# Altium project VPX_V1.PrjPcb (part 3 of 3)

## Sheet Telemetry.SchDoc
size 431 x 279 mm; Date: Not shown in title block; ApprovedBy: Not shown in title block; CheckedBy: Not shown in title block; Author: Not shown in title block; CompanyName: Not shown in title block; Engineer: Not shown in title block; Organization: Not shown in title block; Address1: Not shown in title block; Address2: Not shown in title block; Address3: Not shown in title block; Address4: Not shown in title block; DocumentNumber: 1; Revision: Use project parameter SCH_Rev; SheetNumber: 7; SheetTotal: 8; PageSetup: Record=PageOptions¦CenterHorizontal=True¦CenterVertical=True¦PrintScale=1.00¦XCorrection=1.00¦YCorrection=1.00¦PrintKind=0¦BorderSize=5000000¦LeftOffset=0¦BottomOffset=0¦Orientation=2¦PaperLength=1000¦PaperWidth=1000¦Scale=100¦PaperSource=15¦PrintQuality=600¦MediaType=1¦DitherType=10¦PaperKind=Letter¦PrintScaleMode=1
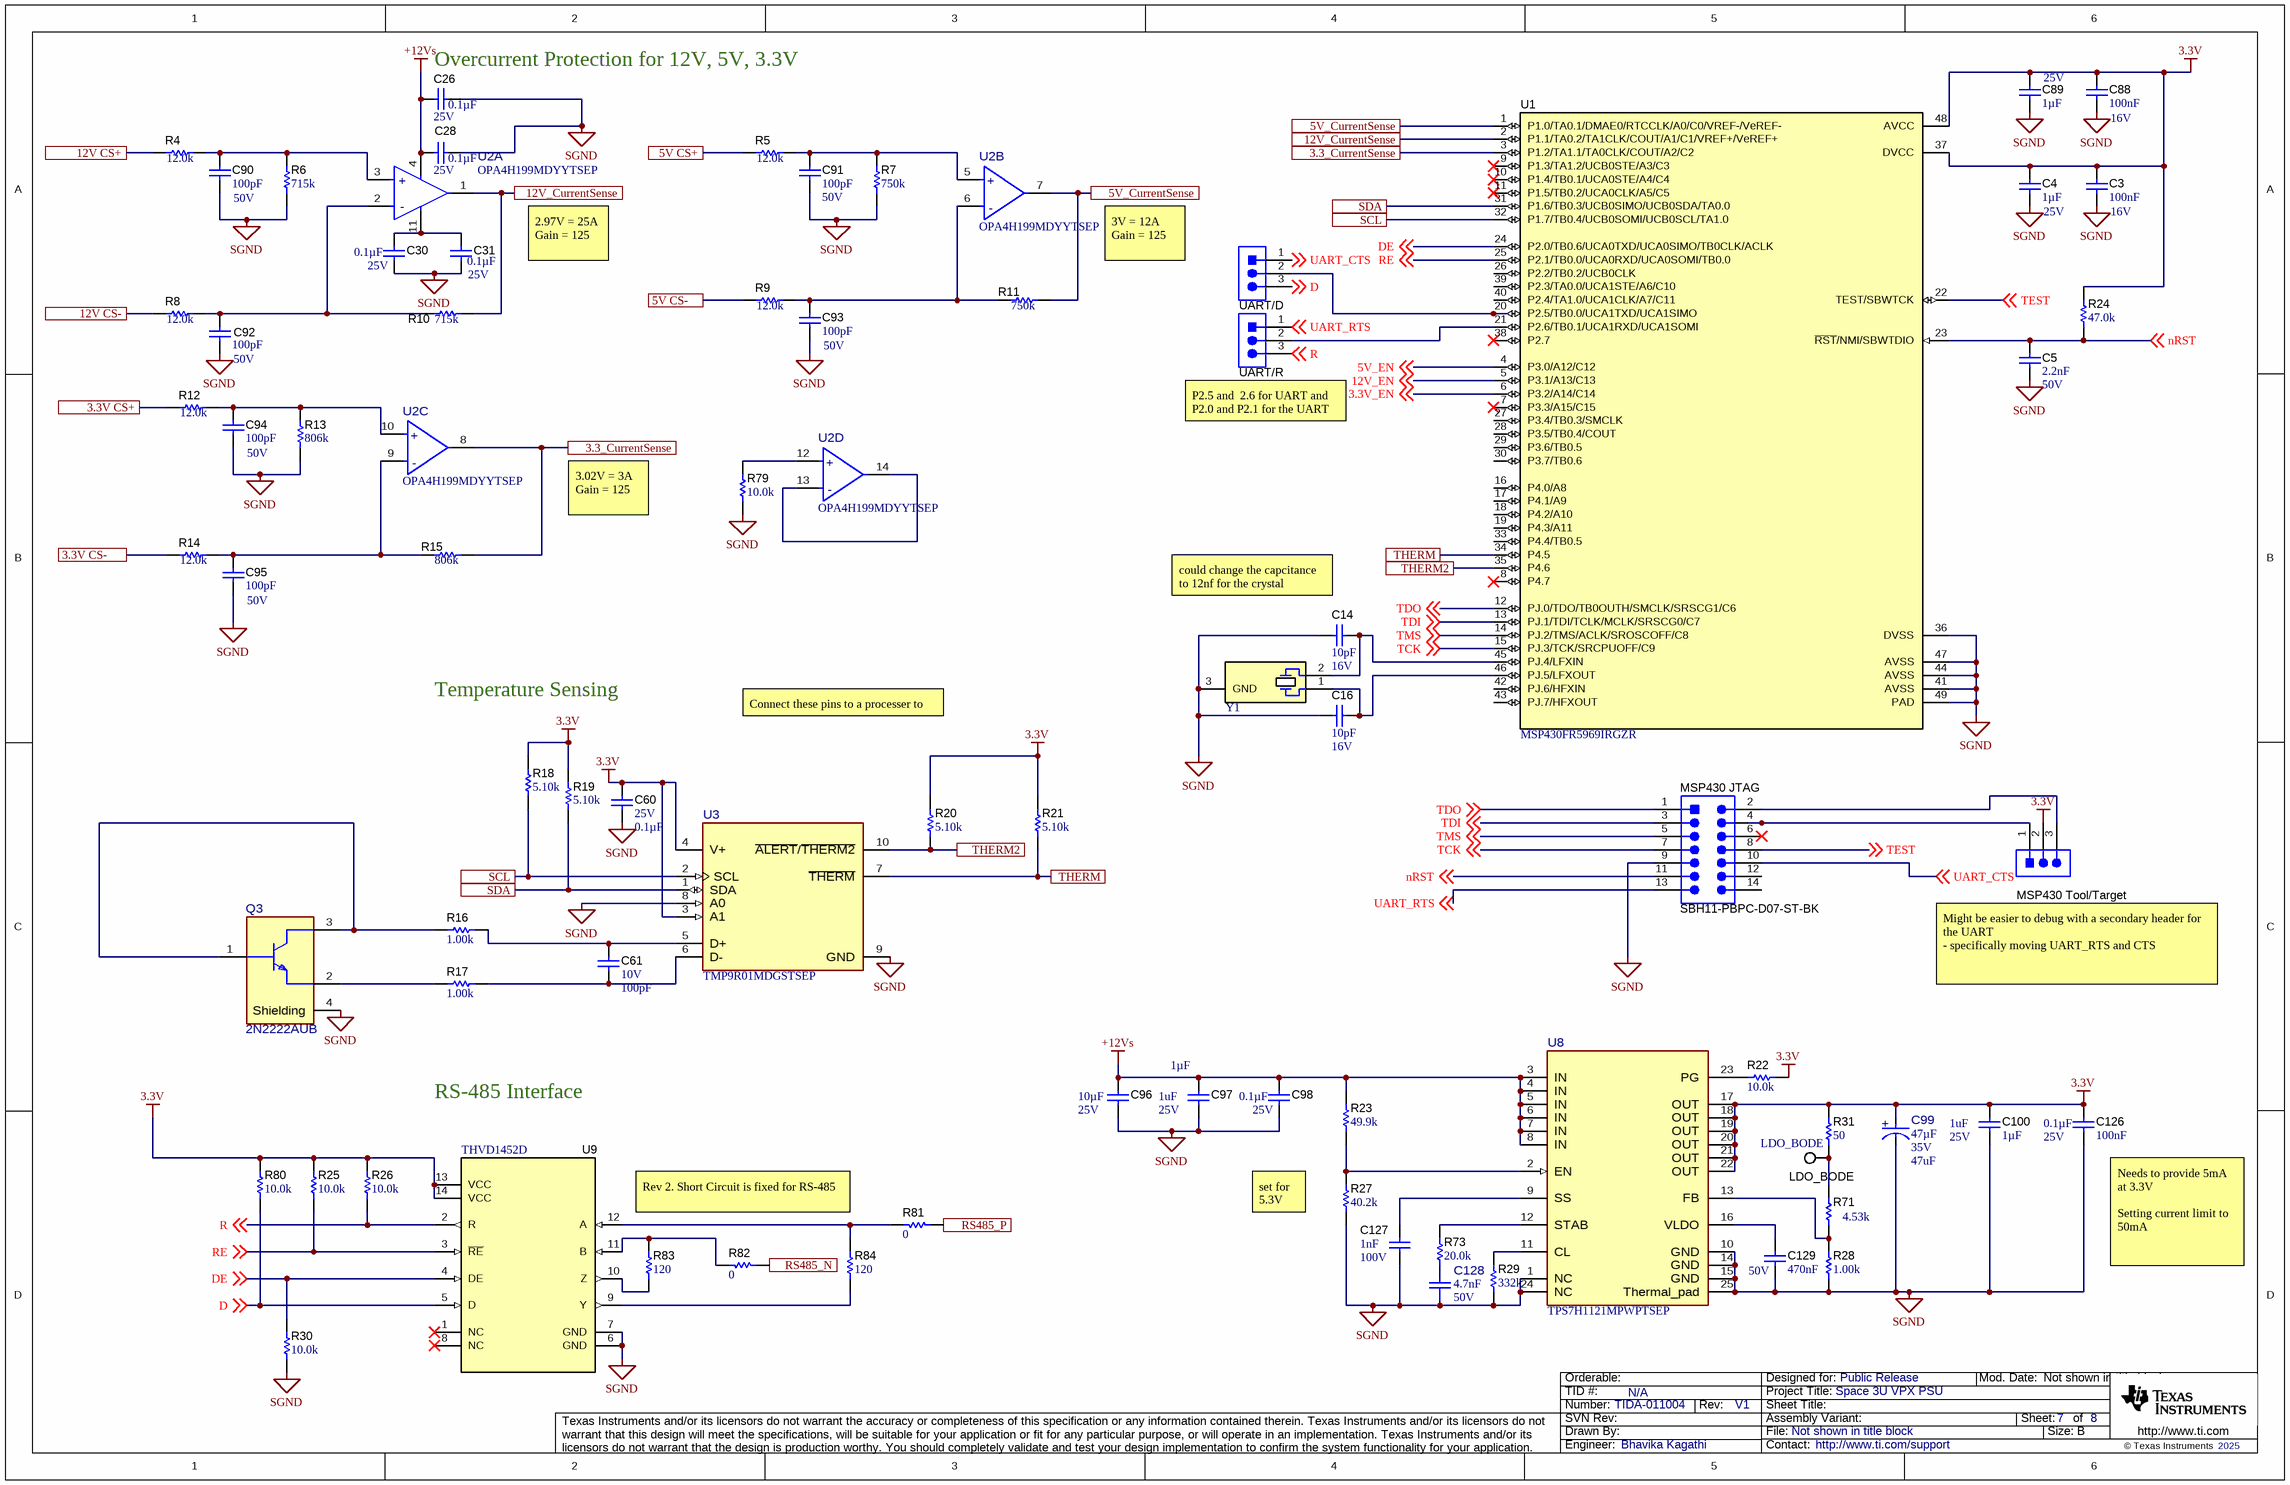
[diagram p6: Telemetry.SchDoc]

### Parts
C3  Cap_F: 100nF  VDC_V: 16V  [0603]  (hidden comment: CL10B104KO8WPNC)
C4  Cap_F: 1µF  VDC_V: 25V  [0603]  (hidden comment: C0603C105K3RACTU)
C5  Cap_F: 2.2nF  VDC_V: 50V  [0603]  (hidden comment: C0603X222K5RACTU)
C14  Cap_F: 10pF  VDC_V: 16V  [0402]  (hidden comment: C0402C100K4GACTU)
C16  Cap_F: 10pF  VDC_V: 16V  [0402]  (hidden comment: C0402C100K4GACTU)
C26  VDC_V: 25V  ValueDisplayed: 0.1µF  [0603]  (hidden comment: GCM188R71E104KA57D)
C28  VDC_V: 25V  ValueDisplayed: 0.1µF  [0603]  (hidden comment: GCM188R71E104KA57D)
C30  VDC_V: 25V  ValueDisplayed: 0.1µF  [0603]  (hidden comment: GCM188R71E104KA57D)
C31  VDC_V: 25V  ValueDisplayed: 0.1µF  [0603]  (hidden comment: GCM188R71E104KA57D)
C60  VDC_V: 25V  ValueDisplayed: 0.1µF  [0603]  (hidden comment: GCM188R71E104KA57D)
C61  VDC_V: 10V  ValueDisplayed: 100pF  [0603]  (hidden comment: 0603ZC101KAT2A)
C88  Cap_F: 100nF  VDC_V: 16V  [0603]  (hidden comment: CL10B104KO8WPNC)
C89  Cap_F: 1µF  VDC_V: 25V  [0603]  (hidden comment: C0603C105K3RACTU)
C90  Cap_F: 100pF  VDC_V: 50V  [0603L]  (hidden comment: CL10B101KB8NNNC)
C91  Cap_F: 100pF  VDC_V: 50V  [0603L]  (hidden comment: CL10B101KB8NNNC)
C92  Cap_F: 100pF  VDC_V: 50V  [0603L]  (hidden comment: CL10B101KB8NNNC)
C93  Cap_F: 100pF  VDC_V: 50V  [0603L]  (hidden comment: CL10B101KB8NNNC)
C94  Cap_F: 100pF  VDC_V: 50V  [0603L]  (hidden comment: CL10B101KB8NNNC)
C95  Cap_F: 100pF  VDC_V: 50V  [0603L]  (hidden comment: CL10B101KB8NNNC)
C96  VDC_V: 25V  ValueDisplayed: 10µF  [0603]  (hidden comment: GRM188R61E106KA73D)
C97  VDC_V: 25V  ValueDisplayed: 1uF  Cap_F: 1µF  [0603]  (hidden comment: C0603C105K3RACTU)
C98  VDC_V: 25V  ValueDisplayed: 0.1µF  [0603]  (hidden comment: GCM188R71E104KA57D)
C99  Cap_F: 47µF  VDC_V: 35V  ValueDisplayed: 47uF  [FP-T510X476M035ATE055_2917-MFG]  (hidden comment: T510X476M035ATE055)
C100  Cap_F: 1µF  VDC_V: 25V  ValueDisplayed: 1uF  [0603]  (hidden comment: C0603C105K3RACTU)
C126  Cap_F: 100nF  VDC_V: 25V  ValueDisplayed: 0.1µF  [0603]  (hidden comment: GCM188R71E104KA57D)
C127  Cap_F: 1nF  VDC_V: 100V  [0603]  (hidden comment: 06031C102JAT2A)
C128  Cap_F: 4.7nF  VDC_V: 50V  [FP-C0603C472J5RAC7867_0603-MFG]  (hidden comment: C0603C472J5RAC7867)
C129  Cap_F: 470nF  VDC_V: 50V  [0603]  (hidden comment: UMK107B7474KA-TR)
LDO_BODE  LDO_BODE  [Keystone5002]
MSP430_JTAG  SBH11-PBPC-D07-ST-BK  [CONN_SBH11-PBPC-D07-ST-BK]
MSP430_Tool/Target  PTT-103-01-L-S  [Samtec_PTT-103-01-x-S]  (value not drawn)
Q3  2N2222AUB  [FP-2N2222AUB_SMT3-IPC_A]
R4  ValueDisplayed: 12.0k  [0603]  (hidden comment: RC0603FR-0712KL)
R5  ValueDisplayed: 12.0k  [0603]  (hidden comment: RC0603FR-0712KL)
R6  ValueDisplayed: 715k  [0603]  (hidden comment: CRCW0603715KFKEA)
R7  ValueDisplayed: 750k  [0603]  (hidden comment: CRCW0603750KFKEA)
R8  ValueDisplayed: 12.0k  [0603]  (hidden comment: RC0603FR-0712KL)
R9  ValueDisplayed: 12.0k  [0603]  (hidden comment: RC0603FR-0712KL)
R10  ValueDisplayed: 715k  [0603]  (hidden comment: CRCW0603715KFKEA)
R11  ValueDisplayed: 750k  [0603]  (hidden comment: CRCW0603750KFKEA)
R12  ValueDisplayed: 12.0k  [0603]  (hidden comment: RC0603FR-0712KL)
R13  ValueDisplayed: 806k  [0603]  (hidden comment: CRCW0603806KFKEA)
R14  ValueDisplayed: 12.0k  [0603]  (hidden comment: RC0603FR-0712KL)
R15  ValueDisplayed: 806k  [0603]  (hidden comment: CRCW0603806KFKEA)
R16  ValueDisplayed: 1.00k  [0603]  (hidden comment: RC0603FR-071KL)
R17  ValueDisplayed: 1.00k  [0603]  (hidden comment: RC0603FR-071KL)
R18  ValueDisplayed: 5.10k  [0603]  (hidden comment: RC0603FR-075K1L)
R19  ValueDisplayed: 5.10k  [0603]  (hidden comment: RC0603FR-075K1L)
R20  ValueDisplayed: 5.10k  [0603]  (hidden comment: RC0603FR-075K1L)
R21  ValueDisplayed: 5.10k  [0603]  (hidden comment: RC0603FR-075K1L)
R22  ValueDisplayed: 10.0k  [0603]  (hidden comment: RC0603FR-0710KL)
R23  ValueDisplayed: 49.9k  [0603]  (hidden comment: ERJ-3EKF4992V)
R24  ValueDisplayed: 47.0k  [0603]  (hidden comment: RC0603FR-0747KL)
R25  ValueDisplayed: 10.0k  [0603]  (hidden comment: CRCW060310K0FKEA)
R26  ValueDisplayed: 10.0k  [0603]  (hidden comment: CRCW060310K0FKEA)
R27  ValueDisplayed: 40.2k  [0603]  (hidden comment: RC0603FR-0740K2L)
R28  ValueDisplayed: 1.00k  [0603]  (hidden comment: CRCW06031K00FKEA)
R29  ValueDisplayed: 332k  [0603]  (hidden comment: CRCW0603332KFKEA)
R30  ValueDisplayed: 10.0k  [0603]  (hidden comment: CRCW060310K0FKEA)
R31  ValueDisplayed: 50  [0603]  (hidden comment: FC0603E50R0BTBST1)
R71  ValueDisplayed: 4.53k  [0603]  (hidden comment: ERJ-3EKF4531V)
R73  ValueDisplayed: 20.0k  [0603]  (hidden comment: RG1608P-203-B-T5)
R79  ValueDisplayed: 10.0k  [0603]  (hidden comment: RT0603BRD0710KL)
R80  ValueDisplayed: 10.0k  [0603]  (hidden comment: CRCW060310K0FKEA)
R81  ValueDisplayed: 0  [0603_HV]  (hidden comment: CRCW06030000Z0EA)
R82  ValueDisplayed: 0  [0603_HV]  (hidden comment: CRCW06030000Z0EA)
R83  ValueDisplayed: 120  [0603]  (hidden comment: RC0603FR-07120RL)
R84  ValueDisplayed: 120  [0603]  (hidden comment: RC0603FR-07120RL)
U1  MSP430FR5969IRGZR  [RGZ0048B]
U2  OPA4H199MDYYTSEP  [DYY0014A-MFG]  (parts A,B,C,D of 4)
U3  TMP9R01MDGSTSEP  [DGS0010A-MFG]
U8  TPS7H1121MPWPTSEP  [PWP0024R-MFG]
U9  THVD1452D  [D0014A_N]
UART/D  PTT-103-01-L-S  [Samtec_PTT-103-01-x-S]  (value not drawn)
UART/R  PTT-103-01-L-S  [Samtec_PTT-103-01-x-S]  (value not drawn)
Y1  MS3V-T1R 32.768KHZ 7.0 PF  [XTAL_MS3V-T1R]  (value not drawn)

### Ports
3.3_CurrentSense, 3.3V CS+, 3.3V CS-, 5V CS+, 5V CS-, 5V_CurrentSense, 12V CS+, 12V CS-, 12V_CurrentSense, RS485_N, RS485_P, SCL, SDA, THERM, THERM2

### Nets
3.3V: C3.1 C4.1 C60.2 C88.1 C89.1 C99.2(ANODE) C100.1 C126.1 MSP430_Tool/Target.2 R18.1 R19.1 R20.1 R21.1 R22.2 R24.1 R25.1 R26.1 R31.2 R80.1 U1.37(DVCC) U1.48(AVCC) U3.3(A1) U3.4(V+) U8.17(OUT) U8.18(OUT) U8.19(OUT) U8.20(OUT) U8.21(OUT) U8.22(OUT) U9.13(VCC) U9.14(VCC)
3.3V_OUT: R14.2 ; port 3.3V CS-
5V: R9.2 ; port 5V CS-
+12Vs: C26.1 C28.2 C96.1 C97.1 C98.1 R23.1 U2.4(V+) U8.3(IN) U8.4(IN) U8.5(IN) U8.6(IN) U8.7(IN) U8.8(IN)
PVIN: R8.2 ; port 12V CS-
SGND: C3.2 C4.2 C5.1 C14.1 C16.1 C26.2 C28.1 C30.2 C31.2 C60.1 C88.2 C89.2 C90.2 C91.2 C92.2 C93.2 C94.2 C95.2 C96.2 C97.2 C98.2 C99.1(CATHODE) C100.2 C126.2 C127.2 C128.1 C129.2 MSP430_JTAG.9 Q3.4(Shielding) R6.2 R7.2 R13.2 R27.2 R28.2 R29.2 R30.2 R79.1 U1.36(DVSS) U1.41(AVSS) U1.44(AVSS) U1.47(AVSS) U1.49(PAD) U3.8(A0) U3.9(GND) U8.1(NC) U8.10(GND) U8.14(GND) U8.15(GND) U8.24(NC) U8.25(Thermal_pad) U9.6(GND) U9.7(GND) Y1.3(GND)
3.3_CurrentSense: R15.1 U1.3(P1.2/TA1.1/TA0CLK/COUT/A2/C2) U2.8(OUT3) ; port 3.3_CurrentSense
3.3V CS+: R12.2 ; port 3.3V CS+
3.3V_EN: U1.6(P3.2/A14/C14) ; off-sheet 3.3V_EN
5V CS+: R5.2 ; port 5V CS+
5V_CurrentSense: R11.1 U1.1(P1.0/TA0.1/DMAE0/RTCCLK/A0/C0/VREF-/VeREF-) U2.7(OUT2) ; port 5V_CurrentSense
5V_EN: U1.4(P3.0/A12/C12) ; off-sheet 5V_EN
12V CS+: R4.2 ; port 12V CS+
12V_CurrentSense: R10.1 U1.2(P1.1/TA0.2/TA1CLK/COUT/A1/C1/VREF+/VeREF+) U2.1(OUT1) ; port 12V_CurrentSense
12V_EN: U1.5(P3.1/A13/C13) ; off-sheet 12V_EN
D: R80.2 U9.5(D) UART/D.3 ; off-sheet D
DE: R30.1 U1.24(P2.0/TB0.6/UCA0TXD/UCA0SIMO/TB0CLK/ACLK) U9.4(DE) ; off-sheet DE
nRST: C5.2 MSP430_JTAG.11 R24.2 U1.23(~{RST}/NMI/SBWTDIO) ; off-sheet nRST
R: R26.2 U9.2(R) UART/R.3 ; off-sheet R
RE: R25.2 U1.25(P2.1/TB0.0/UCA0RXD/UCA0SOMI/TB0.0) U9.3(~{RE}) ; off-sheet RE
RS485_N: R82.2 ; port RS485_N
RS485_P: R81.2 ; port RS485_P
SCL: R18.2 U1.32(P1.7/TB0.4/UCB0SOMI/UCB0SCL/TA1.0) U3.2(SCL) ; port SCL
SDA: R19.2 U1.31(P1.6/TB0.3/UCB0SIMO/UCB0SDA/TA0.0) U3.1(SDA) ; port SDA
TCK: MSP430_JTAG.7 U1.15(PJ.3/TCK/SRCPUOFF/C9) ; off-sheet TCK
TDI: MSP430_JTAG.3 U1.13(PJ.1/TDI/TCLK/MCLK/SRSCG0/C7) ; off-sheet TDI
TDO: MSP430_JTAG.1 U1.12(PJ.0/TDO/TB0OUTH/SMCLK/SRSCG1/C6) ; off-sheet TDO
TEST: MSP430_JTAG.8 U1.22(TEST/SBWTCK) ; off-sheet TEST
THERM: R21.2 U1.34(P4.5) U3.7(~{THERM}) ; port THERM
THERM2: R20.2 U1.35(P4.6) U3.10(~{ALERT}/~{THERM2}) ; port THERM2
TMS: MSP430_JTAG.5 U1.14(PJ.2/TMS/ACLK/SROSCOFF/C8) ; off-sheet TMS
UART_CTS: MSP430_JTAG.10 UART/D.1 ; off-sheet UART_CTS
UART_RTS: MSP430_JTAG.13 UART/R.1 ; off-sheet UART_RTS
NetC14_2: C14.2 U1.45(PJ.4/LFXIN) Y1.2
NetC16_2: C16.2 U1.46(PJ.5/LFXOUT) Y1.1
NetC30_1: C30.1 C31.1 U2.11(V-)
NetC61_1: C61.1 R17.2 U3.6(D-)
NetC61_2: C61.2 R16.2 U3.5(D+)
NetC90_1: C90.1 R4.1 R6.1 U2.3(IN1+)
NetC91_1: C91.1 R5.1 R7.1 U2.5(IN2+)
NetC92_1: C92.1 R8.1 R10.2 U2.2(IN1-)
NetC93_1: C93.1 R9.1 R11.2 U2.6(IN2-)
NetC94_1: C94.1 R12.1 R13.1 U2.10(IN3+)
NetC95_1: C95.1 R14.1 R15.2 U2.9(IN3-)
NetC127_1: C127.1 U8.9(SS)
NetC128_2: C128.2 R73.2
NetC129_1: C129.1 U8.16(VLDO)
NetLDO_BODE_1: LDO_BODE.1 R31.1 R71.1
NetMSP430_JTAG_2: MSP430_JTAG.2 MSP430_Tool/Target.3
NetMSP430_JTAG_4: MSP430_JTAG.4 MSP430_Tool/Target.1
NetQ3_1: Q3.1(Base) Q3.3(Collector) R16.1
NetQ3_2: Q3.2(Emitter) R17.1
NetR22_1: R22.1 U8.23(PG)
NetR23_2: R23.2 R27.1 U8.2(EN)
NetR28_1: R28.1 R71.2 U8.13(FB)
NetR29_1: R29.1 U8.11(CL)
NetR73_1: R73.1 U8.12(STAB)
NetR79_2: R79.2 U2.12(IN4+)
NetR81_1: R81.1 R84.2 U9.12(A)
NetR82_1: R82.1 R83.2 U9.11(B)
NetR83_1: R83.1 U9.10(Z)
NetR84_1: R84.1 U9.9(Y)
NetU1_20: U1.20(P2.5/TB0.0/UCA1TXD/UCA1SIMO) UART/D.2
NetU1_21: U1.21(P2.6/TB0.1/UCA1RXD/UCA1SOMI) UART/R.2
NetU2_13: U2.13(IN4-) U2.14(OUT4)

Not connected (* = marked no-connect by the designer): MSP430_JTAG 6* 12 14; U1 7(P3.3/A15/C15)* 8(P4.7)* 9(P1.3/TA1.2/UCB0STE/A3/C3)* 10(P1.4/TB0.1/UCA0STE/A4/C4)* 11(P1.5/TB0.2/UCA0CLK/A5/C5)* 16(P4.0/A8) 17(P4.1/A9) 18(P4.2/A10) 19(P4.3/A11) 26(P2.2/TB0.2/UCB0CLK) 27(P3.4/TB0.3/SMCLK) 28(P3.5/TB0.4/COUT) 29(P3.6/TB0.5) 30(P3.7/TB0.6) 33(P4.4/TB0.5) 38(P2.7)* 39(P2.3/TA0.0/UCA1STE/A6/C10) 40(P2.4/TA1.0/UCA1CLK/A7/C11) 42(PJ.6/HFXIN) 43(PJ.7/HFXOUT); U9 1(NC)* 8(NC)*

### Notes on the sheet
- (near C26) Overcurrent Protection for 12V, 5V, 3.3V
- 2.97V = 25A
  Gain = 125
- 3V = 12A
  Gain = 125
- (near UART/R) P2.5 and  2.6 for UART and P2.0 and P2.1 for the UART channel
- 3.02V = 3A
  Gain = 125
- (near C14) could change the capcitance to 12nf for the crystal
- Temperature Sensing
- Connect these pins to a processer to pins with interrupt
- Might be easier to debug with a secondary header for the UART
  - specifically moving UART_RTS and CTS
- RS-485 Interface
- Rev 2. Short Circuit is fixed for RS-485
- set for 5.3V
- (near C126) Needs to provide 5mA at 3.3V
  Setting current limit to 50mA

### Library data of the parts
C3 C88 = CMP-0085536-1: CAP, CERM, 0.1 µF, 16 V,+/- 10%, X7R, 0603; Manufacturer: Samsung Electro-Mechanics; SizeArea_mm2: 1.28; SizeY_mm: 0.8; AEC Category: Q200; Polarized: N; AEC Qualified: Y; ValueDisplayed: 0.1µF; TaMax_C: 125°C; SizeZ_mm: 1; U/M: EA; SizeX_mm: 1.6; Value: 0.1uF; TaMin_C: -55°C; SizeAreaWB_mm2: 4.68
C4 C89 = CMP-0006867-4: CAP, CERM, 1 uF, 25 V, +/- 10%, X7R, 0603; Manufacturer: Kemet; TaMin_C: -55°C; Polarized: N; SizeAreaWB_mm2: 4.68; Value1: Unknown; U/M: EA; Value: 1uF; TaMax_C: 125°C; SizeZ_mm: 1; SizeX_mm: 1.6; SizeY_mm: 0.8; SizeArea_mm2: 1.28; AEC Category: Q200
C5 = CMP-0006983-4: CAP, CERM, 2200 pF, 50 V, +/- 10%, X7R, 0603; Manufacturer: Kemet; Value1: Unknown; ValueDisplayed: 2200pF; SizeZ_mm: 1; AEC Category: Q200; TaMin_C: -55°C; SizeY_mm: 0.8; Polarized: N; SizeAreaWB_mm2: 4.68; SizeArea_mm2: 1.28; TaMax_C: 125°C; SizeX_mm: 1.6; Value: 2200pF; U/M: EA
C14 C16 = CMP-0079539-1: CAP, CERM, 10 pF, 16 V,+/- 10%, C0G, 0402; Manufacturer: Kemet; SizeZ_mm: 0.6; AEC Category: Q200; AEC Qualified: N; Green_REACh: Passed; TaMin_C: -55°C; Green_Lifecycle: Active; SizeY_mm: 0.5; SizeAreaWB_mm2: 3; TaMax_C: 125°C; SizeX_mm: 1; Value: 10pF; U/M: EA
C26 C28 C30 C31 C60 C98 C126 = CMP-0084679-1: CAP, CERM, 0.1 µF, 25 V,+/- 10%, X7R, AEC-Q200 Grade 1, 0603; Manufacturer: MuRata; SizeZ_mm: 1; AEC Category: Q200; AEC Qualified: Y; TaMin_C: -55°C; SizeY_mm: 0.8; Polarized: N; SizeAreaWB_mm2: 4.68; SizeArea_mm2: 1.28; TaMax_C: 125°C; SizeX_mm: 1.6; Value: 0.1uF; U/M: EA
C61 = CMP-0006812-4: CAP, CERM, 100 pF, 10 V, +/- 10%, X7R, 0603; Manufacturer: AVX; Value1: Unknown; SizeZ_mm: 1; AEC Category: Q200; AEC Qualified: N; TaMin_C: -55°C; SizeY_mm: 0.8; SizeAreaWB_mm2: 4.68; SizeArea_mm2: 1.28; TaMax_C: 125°C; SizeX_mm: 1.6; Value: 100pF; U/M: EA
C90-C95 = CMP-0083857-1: CAP, CERM, 100 pF, 50 V,+/- 10%, X7R, 0603; Manufacturer: Samsung Electro-Mechanics; TaMin_C: -55°C; Polarized: N; SizeAreaWB_mm2: 4.68; U/M: EA; Value: 100pF; TaMax_C: 125°C; SizeZ_mm: 1; SizeX_mm: 1.6; SizeY_mm: 0.8; Cap_Case: 0603; SizeArea_mm2: 1.28; AEC Category: Q200
C96 = CMP-0860569-1: CAP, CERM, 10 µF, 25 V,+/- 10%, X5R, 0603; Manufacturer: MuRata; SizeZ_mm: 1; AEC Category: Q200; AEC Qualified: N; TaMin_C: -55°C; SizeY_mm: 0.8; SizeAreaWB_mm2: 4.68; SizeArea_mm2: 1.28; TaMax_C: 85°C; SizeX_mm: 1.6; Value: 10uF; U/M: EA
C97 C100 = CMP-0006867-4: CAP, CERM, 1 uF, 25 V, +/- 10%, X7R, 0603; Manufacturer: Kemet; Value1: Unknown; SizeZ_mm: 1; AEC Category: Q200; TaMin_C: -55°C; SizeY_mm: 0.8; Polarized: N; SizeAreaWB_mm2: 4.68; SizeArea_mm2: 1.28; TaMax_C: 125°C; SizeX_mm: 1.6; Value: 1uF; U/M: EA
C99 = CMP-0121724-1: 47 µF Molded Tantalum Capacitors 35 V 2917 (7343 Metric) 55mOhm; Manufacturer: Kemet; SizeZ_mm: 4.3mm; AEC Qualified: No; IRMS_A: 2.216A; Value: 47µF; Tolerance_%: 20%; Esr: 55m; Leakage Current: 16.5uA; Life: 2000Hours
C127 = CMP-0006723-4: CAP, CERM, 1000 pF, 100 V, +/- 5%, X7R, 0603; Manufacturer: AVX; TaMin_C: -55°C; Polarized: N; SizeAreaWB_mm2: 4.68; Value1: 0.276 ohm; U/M: EA; Value: 1000pF; TaMax_C: 125°C; SizeZ_mm: 1; SizeX_mm: 1.6; SizeY_mm: 0.8; SizeArea_mm2: 1.28; AEC Category: Q200; ESR_ohm: 0.276
C128 = CMP-0120173-1: 4700 pF ±5% 50V Ceramic Capacitor X7R 0603 (1608 Metric); Manufacturer: KEMET; TempCo: 15%; Value: 4.7nF; SizeZ_mm: 0.87mm; AEC Qualified: No; ValueDisplayed: 4700pF
C129 = CMP-0007509-4: CAP, CERM, 0.47 uF, 50 V, +/- 10%, X7R, 0603; Manufacturer: Taiyo Yuden; TaMin_C: -55°C; Polarized: N; SizeAreaWB_mm2: 4.68; Value1: Unknown; U/M: EA; Value: 0.47uF; TaMax_C: 125°C; SizeZ_mm: 1; SizeX_mm: 1.6; SizeY_mm: 0.8; SizeArea_mm2: 1.28; AEC Category: Q200
LDO_BODE = CMP-0055139-2: Test Point, Miniature, White, TH; Manufacturer: Keystone Electronics; ContactFinish: Silver; CT: TRUE; CNHeader: FALSE; Green_Lifecycle: Active; Green_REACh: Passed
MSP430_JTAG = CMP-0054695-2: Header (shrouded), 100 mil, 7x2, Gold, TH; Manufacturer: Sullins Connector Solutions; Green_REACh: Incomplete; Green_Lifecycle: Not Set
MSP430_Tool/Target UART/D UART/R = CMP-0055571-1: Header, 2mm, 3x1, Gold, TH; Manufacturer: Samtec; Current_A: 2.9A; Shrouded: N; CT: FALSE; Cert_UL: Y; Pitch_mm: 2; CNHeader: TRUE; Gender: Male
Q3 = CMP-0098458-1: Bipolar (BJT) Transistor NPN 50 V 800 mA 500 mW Surface Mount 3-SMD; Manufacturer: Microchip; Vcesat1_V: 1V; IcRated_A: 800mA; SizeZ_mm: 1.42mm; AEC Qualified: No; HfeMax: 300; Value: 50V; NPN: 1; Collector Base Voltage: 75V; Emitter Base Voltage: 6V; Hfe Min: 100; Hfe Ss Min: 50; Hfe Ss Testic: 1mA; Hfe Ss Testvce: 10V; Hfe Testic: 150mA; Power_W: 0.5W; Rthja Max: 325°C/W; TJmax_C: +200°C
R4 R5 R8 R9 R12 R14 = CMP-0022779-5: RES, 12.0 k, 1%, 0.1 W, 0603; Manufacturer: Yageo; Power_W: 100mW; TempCo: 100 ppm/C; Value: 12.0k; Res_ohm: 12k; SizeZ_mm: 1; AEC Qualified: N; VDC_V: 75V; Value_Code: 12k0; SizeX_mm: 1.6; SizeY_mm: 0.8; Value2: 0.1W; SizeArea_mm2: 1.28; AEC Category: Q200; SizeAreaWB_mm2: 4.68
R6 R10 = CMP-0022579-4: RES, 715 k, 1%, 0.1 W, AEC-Q200 Grade 0, 0603; Manufacturer: Vishay-Dale; Power_W: 100mW; TempCo: 100 ppm/C; Value: 715k; SizeZ_mm: 1; AEC Qualified: Y; VDC_V: 75V; AEC Grade: 0; EIA_Code: E96; SizeX_mm: 1.6; SizeY_mm: 0.8; Value2: 0.1W; SizeArea_mm2: 1.28; AEC Category: Q200
R7 R11 = CMP-0022587-4: RES, 750 k, 1%, 0.1 W, AEC-Q200 Grade 0, 0603; Manufacturer: Vishay-Dale; Power_W: 100mW; TempCo: 100 ppm/C; Value: 750k; SizeZ_mm: 1; AEC Qualified: Y; VDC_V: 75V; AEC Grade: 0; EIA_Code: E96; SizeX_mm: 1.6; SizeY_mm: 0.8; Value2: 0.1W; SizeArea_mm2: 1.28; AEC Category: Q200
R13 R15 = CMP-0022614-3: RES, 806 k, 1%, 0.1 W, AEC-Q200 Grade 0, 0603; Manufacturer: Vishay-Dale; Power_W: 100mW; TempCo: 100 ppm/C; Value: 806k; SizeZ_mm: 1; AEC Qualified: Y; VDC_V: 75V; AEC Grade: 0; EIA_Code: E96; SizeX_mm: 1.6; SizeY_mm: 0.8; Value2: 0.1W; SizeArea_mm2: 1.28; AEC Category: Q200
R16 R17 = CMP-0022895-5: RES, 1.00 k, 1%, 0.1 W, 0603; Manufacturer: Yageo; Power_W: 100mW; TempCo: 100 ppm/C; Value: 1.00k; Res_ohm: 1k; SizeZ_mm: 1; AEC Qualified: N; VDC_V: 75V; Value_Code: 1k00; EIA_Code: E96; SizeX_mm: 1.6; SizeY_mm: 0.8; Value2: 0.1W; SizeArea_mm2: 1.28; AEC Category: Q200; SizeAreaWB_mm2: 4.68
R18-R21 = CMP-0023198-5: RES, 5.10 k, 1%, 0.1 W, 0603; Manufacturer: Yageo; Power_W: 100mW; TempCo: 100 ppm/C; Value: 5.10k; Res_ohm: 5.1k; SizeZ_mm: 1; AEC Qualified: N; VDC_V: 75V; Value_Code: 5k10; SizeX_mm: 1.6; SizeY_mm: 0.8; Value2: 0.1W; SizeArea_mm2: 1.28; AEC Category: Q200; SizeAreaWB_mm2: 4.68
R22 = CMP-0022746-5: RES, 10.0 k, 1%, 0.1 W, 0603; Manufacturer: Yageo; Power_W: 100mW; TempCo: 100 ppm/C; Value: 10.0k; Res_ohm: 10k; SizeZ_mm: 1; AEC Qualified: N; VDC_V: 75V; Value_Code: 10k0; EIA_Code: E96; SizeX_mm: 1.6; SizeY_mm: 0.8; Value2: 0.1W; SizeArea_mm2: 1.28; AEC Category: Q200; SizeAreaWB_mm2: 4.68
R23 = CMP-0022705-3: RES, 49.9 k, 1%, 0.1 W, AEC-Q200 Grade 0, 0603; Manufacturer: Panasonic; Power_W: 100mW; TempCo: 100 ppm/C; Value: 49.9k; SizeZ_mm: 1; AEC Qualified: Y; VDC_V: 75V; AEC Grade: 0; Value_Code: 49k9; EIA_Code: E96; SizeX_mm: 1.6; SizeY_mm: 0.8; Value2: 0.1W; SizeArea_mm2: 1.28; AEC Category: Q200; U/M: EA
R24 = CMP-0023133-5: RES, 47.0 k, 1%, 0.1 W, 0603; Manufacturer: Yageo; Power_W: 100mW; TempCo: 100 ppm/C; Value: 47.0k; Res_ohm: 47k; SizeZ_mm: 1; AEC Qualified: N; VDC_V: 75V; Value_Code: 47k0; SizeX_mm: 1.6; SizeY_mm: 0.8; Value2: 0.1W; SizeArea_mm2: 1.28; AEC Category: Q200; SizeAreaWB_mm2: 4.68
R25 R26 R30 R80 = CMP-0021998-4: RES, 10.0 k, 1%, 0.1 W, AEC-Q200 Grade 0, 0603; Manufacturer: Vishay-Dale; Power_W: 100mW; TempCo: 100 ppm/C; Value: 10.0k; Res_ohm: 10k; SizeZ_mm: 1; AEC Qualified: Y; VDC_V: 75V; AEC Grade: 0; Value_Code: 10k0; EIA_Code: E96; SizeX_mm: 1.6; SizeY_mm: 0.8; Value2: 0.1W; SizeArea_mm2: 1.28; AEC Category: Q200
R27 = CMP-0023098-5: RES, 40.2 k, 1%, 0.1 W, 0603; Manufacturer: Yageo; Power_W: 100mW; TempCo: 100 ppm/C; Value: 40.2k; SizeZ_mm: 1; AEC Qualified: N; VDC_V: 75V; Value_Code: 40k2; EIA_Code: E96; SizeX_mm: 1.6; SizeY_mm: 0.8; Value2: 0.1W; SizeArea_mm2: 1.28; AEC Category: Q200; SizeAreaWB_mm2: 4.68
R28 = CMP-0022109-5: RES, 1.00 k, 1%, 0.1 W, AEC-Q200 Grade 0, 0603; Manufacturer: Vishay-Dale; Power_W: 100mW; TempCo: 100 ppm/C; Value: 1.00k; Res_ohm: 1k; SizeZ_mm: 1; AEC Qualified: Y; VDC_V: 75V; AEC Grade: 0; Value_Code: 1k00; EIA_Code: E96; SizeX_mm: 1.6; SizeY_mm: 0.8; Value2: 0.1W; SizeArea_mm2: 1.28; AEC Category: Q200
R29 = CMP-0022336-4: RES, 332 k, 1%, 0.1 W, AEC-Q200 Grade 0, 0603; Manufacturer: Vishay-Dale; Power_W: 100mW; TempCo: 100 ppm/C; Value: 332k; SizeZ_mm: 1; AEC Qualified: Y; VDC_V: 75V; AEC Grade: 0; EIA_Code: E96; SizeX_mm: 1.6; SizeY_mm: 0.8; Value2: 0.1W; SizeArea_mm2: 1.28; AEC Category: Q200
R31 = CMP-0023387-3: RES, 50, 0.1%, 0.125 W, 0603; Manufacturer: Vishay Thin Film; Power_W: 125mW; TempCo: 25 ppm/C; Value_Code: 50R0; U/M: EA; Value: 50; SizeX_mm: 1.6; SizeY_mm: 0.8; SizeZ_mm: 1; Value2: 0.125W; SizeArea_mm2: 1.28; AEC Qualified: N; VDC_V: 50V; AEC Category: Q200
R71 = CMP-0022703-3: RES, 4.53 k, 1%, 0.1 W, AEC-Q200 Grade 0, 0603; Manufacturer: Panasonic; Power_W: 100mW; TempCo: 100 ppm/C; Value: 4.53k; SizeZ_mm: 1; AEC Qualified: Y; VDC_V: 75V; AEC Grade: 0; Value_Code: 4k53; EIA_Code: E96; SizeX_mm: 1.6; SizeY_mm: 0.8; Value2: 0.1W; SizeArea_mm2: 1.28; AEC Category: Q200; U/M: EA
R73 = CMP-0023464-3: RES, 20.0 k, 0.1%, 0.1 W, 0603; Manufacturer: Susumu Co Ltd; Power_W: 100mW; TempCo: 25 ppm/C; Value: 20.0k; Res_ohm: 20k; SizeZ_mm: 1; VDC_V: 75V; Value_Code: 20k0; EIA_Code: E192; SizeX_mm: 1.6; SizeY_mm: 0.8; Value2: 0.1W; SizeArea_mm2: 1.28; AEC Category: Q200; U/M: EA
R79 = CMP-0023653-3: RES, 10.0 k, 0.1%, 0.1 W, 0603; Manufacturer: Yageo America; Power_W: 100mW; TempCo: 25 ppm/C; Value_Code: 10k0; Value: 10.0k; EIA_Code: E192; Res_ohm: 10k; SizeX_mm: 1.6; SizeY_mm: 0.8; SizeZ_mm: 1; Value2: 0.1W; SizeArea_mm2: 1.28; VDC_V: 75V; AEC Category: Q200; U/M: EA
R81 R82 = CMP-0025697-4: RES, 0, 5%, 0.1 W, AEC-Q200 Grade 0, 0603; Manufacturer: Vishay-Dale; Power_W: 100mW; TempCo: 200 ppm/C; Value_Code: 0000; Value: 0; EIA_Code: E24; SizeX_mm: 1.6; SizeY_mm: 0.8; SizeZ_mm: 1; Value2: 0.1W; SizeArea_mm2: 1.28; AEC Qualified: Y; VDC_V: 75V; AEC Category: Q200
R83 R84 = CMP-0022769-5: RES, 120, 1%, 0.1 W, 0603; Manufacturer: Yageo; Power_W: 100mW; TempCo: 100 ppm/C; Value: 120; SizeZ_mm: 1; AEC Qualified: N; VDC_V: 75V; Value_Code: 120R; SizeX_mm: 1.6; SizeY_mm: 0.8; Value2: 0.1W; SizeArea_mm2: 1.28; AEC Category: Q200; SizeAreaWB_mm2: 4.68
U1 = CMP-0066503-2: MSP430FR5969 16 MHz Ultra-Low-Power Microcontroller featuring 64 KB FRAM, 2 KB SRAM, 40 IO, RGZ0048B (VQFN-48); Manufacturer: Texas Instruments; Alternate PartNumber: MSP430FR5969IRGZT; SizeX_mm: 7; CompType: IC; SizeZ_mm: 1; SizeArea_mm2: 49; SizeAreaWB_mm2: 81; U/M: EA; Green_Lifecycle: Active; Green_REACh: Passed
U2 = CMP-0037180-1: Space-enhanced-product, quad, 40-V 4.5-MHz rail-to-rail input and output operational amplifier 14-SOT-23-THIN -55 to +125; Manufacturer: Texas Instruments; SizeZ_mm: 1.1mm; AEC Qualified: No; Gain Bandwidth: 4.5MHz; Input Bias Current: 0.00001uA; Input Offset Voltage: 0.125mV; Max Dual Supply Voltage: 20V; Max Supply Voltage: 40V; Min Dual Supply Voltage: 1.35V; Min Supply Voltage: 2.7V; Nominal Supply Current: 560uA; Number Of Channels: 4; Output Current Per Channel: 75mA; Response Time: 2.5us; Standoff Height: 0mm; TaMax_C: +125°C; TaMin_C: -55°C; TJmax_C: +150°C; Voltage Gain: 145dB
U3 = CMP-0121240-1: High-Accuracy, Radiation-Hardness-Assured (RHA) Remote and Local Temperature Sensor; Manufacturer: Texas Instruments; SizeZ_mm: 1.1mm; AEC Qualified: No; Interface: 2-Wire,SMBus; Max Supply Voltage: 3.6V; Min Supply Voltage: 1.7V; Operating Supply Current: 3-400uA; Resolution: 12bits; Sensor Output: SMBus; Standoff Height: 0.05mm; TaMax_C: +125°C; TaMin_C: -55°C; TJmax_C: +150°C
U8 = CMP-0122232-1: 2.25 V to 14-V Input, 2-A, Radiation Hardened LDO Regulator; Manufacturer: Texas Instruments; SizeZ_mm: 1.2mm; AEC Qualified: No; Accuracy Percentage: 1.5%; Dropout Voltage: 1000mV; Max Supply Voltage: 14V; Min Supply Voltage: 2.25V; Nominal Supply Current: 8-10mA; Number Of Outputs: 1; Output Type: AdjustableProgrammable; Output Voltage: 0.6-13.9V; Standoff Height: 0.05mm; TJmax_C: +125°C
U9 = CMP-0081980-1: 3.3-V to 5-V RS-485 Transceivers With +/-18-kV IEC ESD Protection, D0014A (SOIC-14); Manufacturer: Texas Instruments; Alternate PartNumber: THVD1452DR; AEC Qualified: N; SizeZ_mm: 1.75; SizeAreaWB_mm2: 85.2; SizeX_mm: 6; SizeY_mm: 8.65; SizeArea_mm2: 51.9; CompType: IC; AEC Category: Q200
Y1 = CMP-0004695-4: Crystal, 32.768 KHz, 7pF, SMD; Manufacturer: Micro Crystal AG; TaMax_C: 85°C; TaMin_C: -40°C; AEC Category: Q200; AEC Qualified: N

## Sheet Connector.SchDoc
size 431 x 558 mm; Date: Not shown in title block; ApprovedBy: Not shown in title block; CheckedBy: Not shown in title block; Author: Not shown in title block; CompanyName: Not shown in title block; Engineer: Not shown in title block; Organization: Not shown in title block; Address1: Not shown in title block; Address2: Not shown in title block; Address3: Not shown in title block; Address4: Not shown in title block; DocumentNumber: 1; Revision: Use project parameter SCH_Rev; SheetNumber: 8; SheetTotal: 8; PageSetup: Record=PageOptions¦CenterHorizontal=True¦CenterVertical=True¦PrintScale=1.00¦XCorrection=1.00¦YCorrection=1.00¦PrintKind=0¦BorderSize=5000000¦LeftOffset=0¦BottomOffset=0¦Orientation=2¦PaperLength=1000¦PaperWidth=1000¦Scale=100¦PaperSource=15¦PrintQuality=600¦MediaType=1¦DitherType=10¦PaperKind=Letter¦PrintScaleMode=1
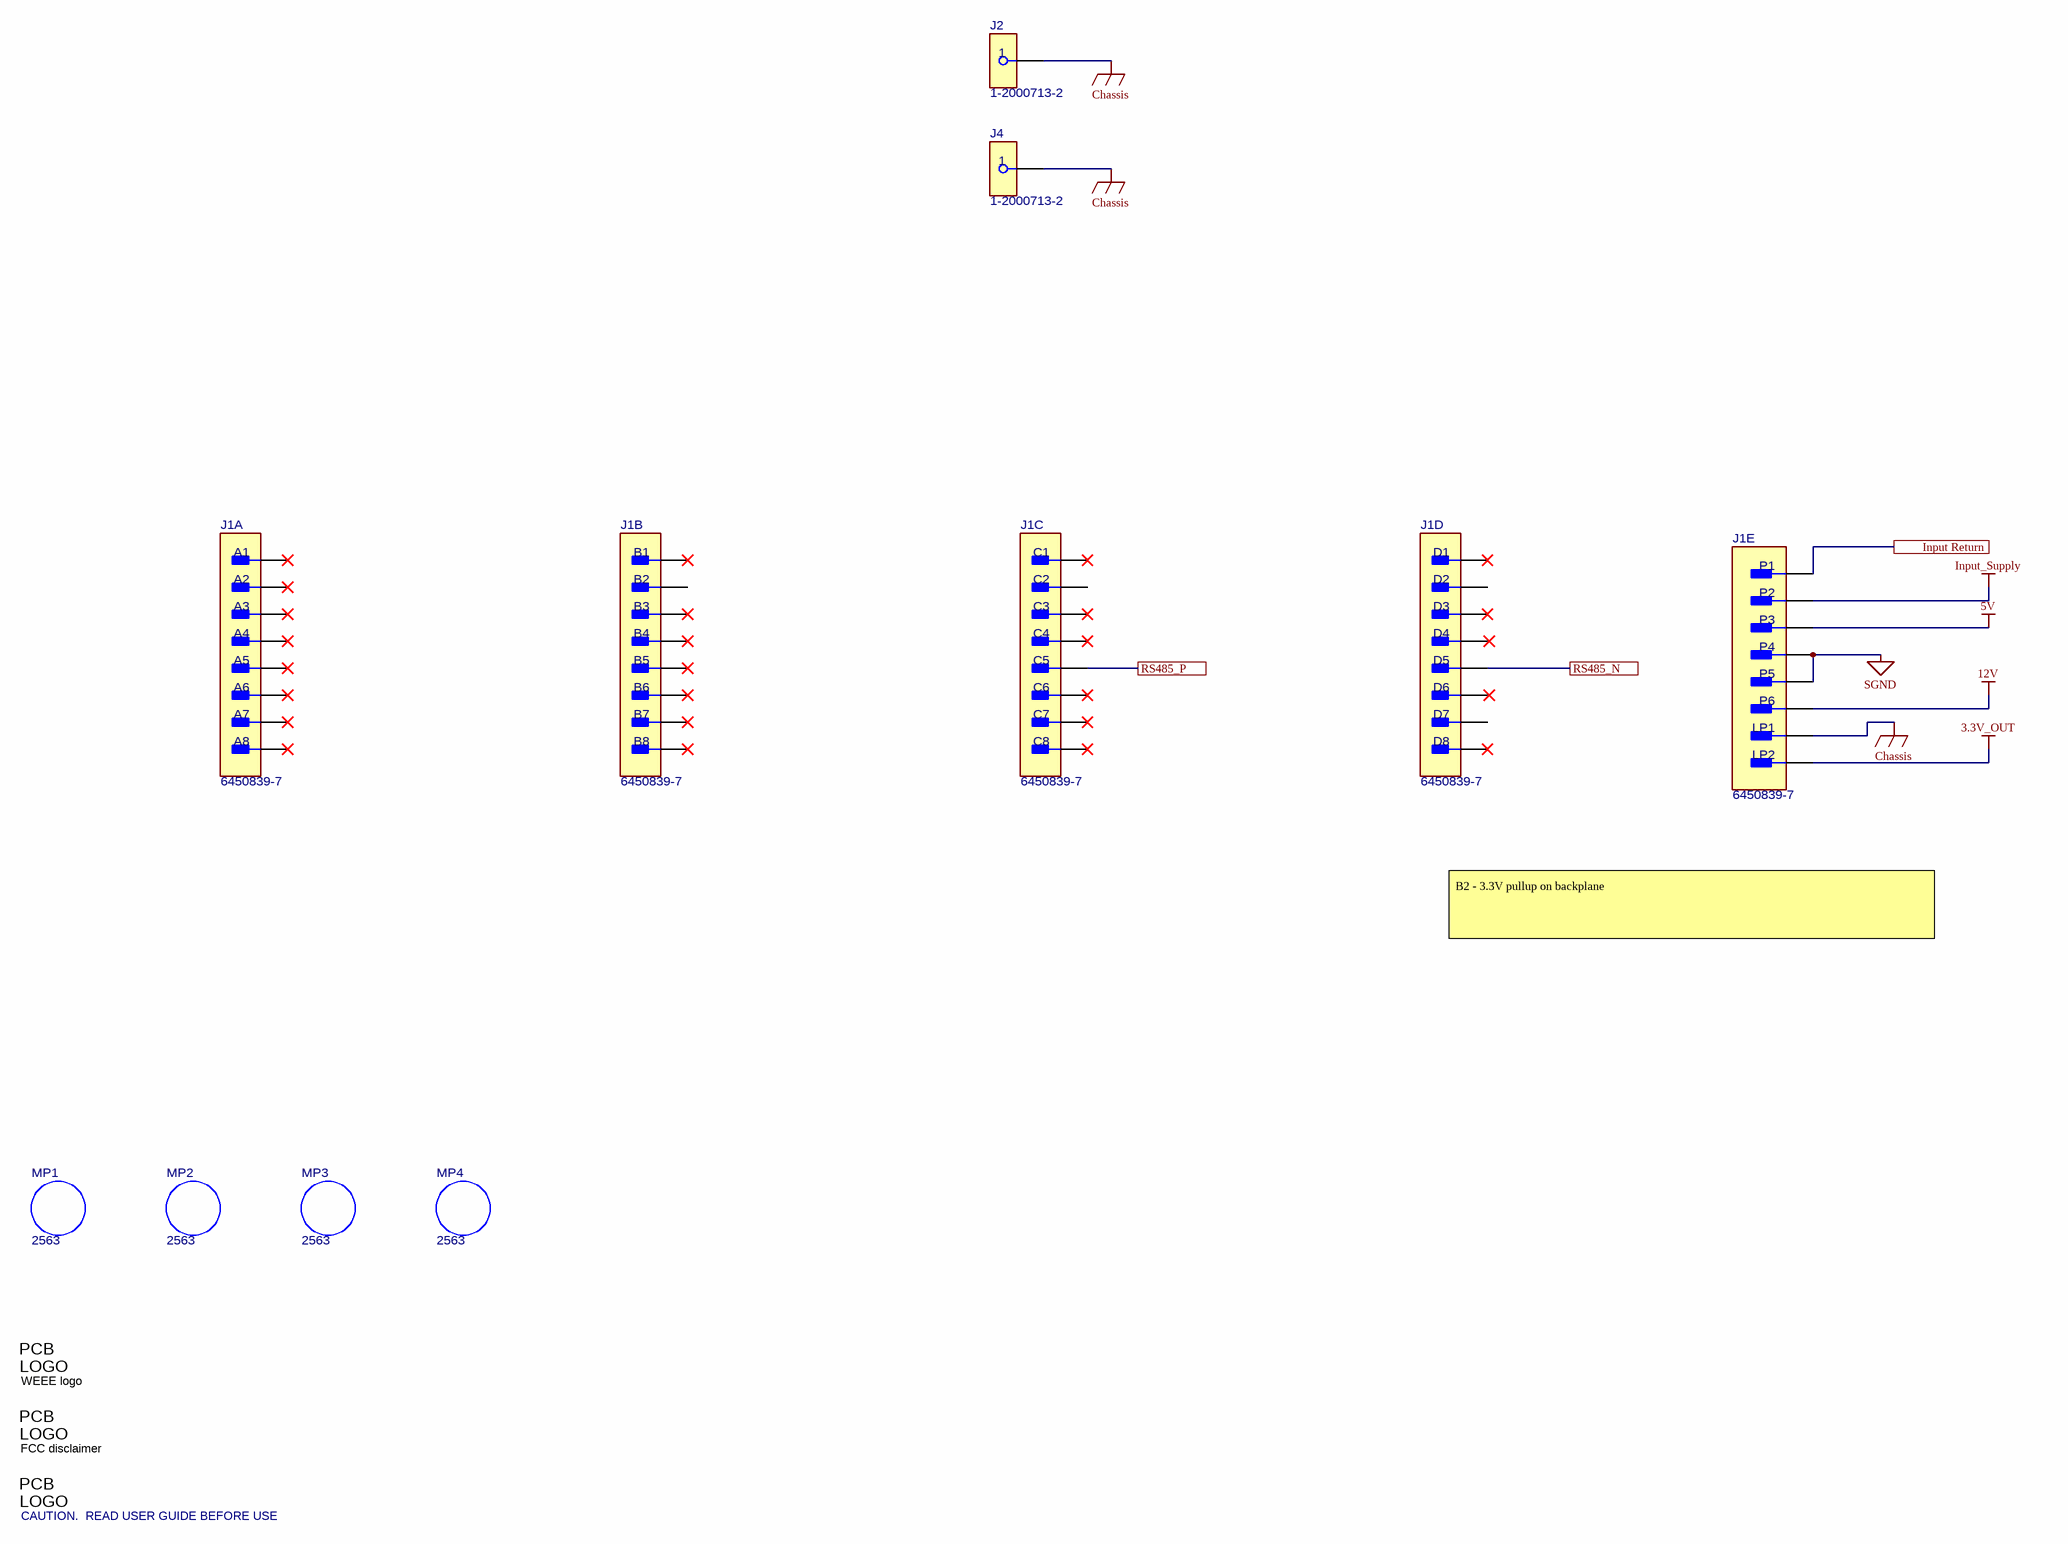
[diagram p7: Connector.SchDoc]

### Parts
J1  6450839-7  [FP-6450839-7_CONN_PWR_HDR_8-32-MFG]  (parts A,B,C,D,E of 5)
J2  1-2000713-2  [FP-1-2000713-2_HDR1-MFG]
J4  1-2000713-2  [FP-1-2000713-2_HDR1-MFG]
Logo1  WEEE logo  [WEEE_Minimum]  (no BOM)
Logo2  FCC disclaimer  [FCC_disclaimer]  (no BOM)
Logo3  CAUTION.  READ USER GUIDE BEFORE USE  [IEC_Caution_Small]  (no BOM)
MP1  2563  [FP-2563_RUBBER_BUMPER-MFG]
MP2  2563  [FP-2563_RUBBER_BUMPER-MFG]
MP3  2563  [FP-2563_RUBBER_BUMPER-MFG]
MP4  2563  [FP-2563_RUBBER_BUMPER-MFG]

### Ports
Input Return, RS485_N, RS485_P

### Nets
3.3V_OUT: J1.LP2
5V: J1.P3
12V: J1.P6  [project net PVIN]
Chassis: J1.LP1 J2.1 J4.1
Input_Supply: J1.P2
SGND: J1.P4 J1.P5
Input Return: J1.P1 ; port Input Return
RS485_N: J1.D5 ; port RS485_N
RS485_P: J1.C5 ; port RS485_P

Not connected (* = marked no-connect by the designer): J1 A1* A2* A3* A4* A5* A6* A7* A8* B1* B2 B3* B4* B5* B6* B7* B8* C1* C2 C3* C4* C6* C7* C8* D1* D2 D3* D4 D6 D7 D8*

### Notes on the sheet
- B2 - 3.3V pullup on backplane

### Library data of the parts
J1 = CMP-0127211-1: Conn Power HDR 8Power/32Signal POS 2.54mm/5.08mm Solder RA Thru-Hole 88 Terminal 1 Port; Manufacturer: TE Connectivity; ContactFinish: Gold,Nickel; Current_A: 50A; Voltage_V: 300V; AEC Qualified: No; Conn Gender: Male; Conn Orientation: Right Angle
J2 J4 = CMP-0127380-1: Connector Guide Module For MULTIGIG RT 2-R Series; Manufacturer: TE Connectivity; ContactFinish: Gold,Nickel; AEC Qualified: No; Conn Gender: Female; Conn Orientation: Right Angle; Is Female: yes; SizeZ_mm: 9.63mm
Logo1 = CMP-0074769-1
Logo2 = CMP-0074847-1: FCC_disclaimer; Library Reference: Logo
Logo3 = CMP-0074836-1: IEC 61010-1 Caution Warning; SymbolCreator: a0412235; Lib Reference: IEC_Caution
MP1-MP4 = CMP-0091591-1: Bumper / Feet, Stick On, Pack, Adhesive, 6.4 mm, 12.7 mm, Round, Transparent; Manufacturer: Multicomp; SizeZ_mm: 6.9mm; AEC Qualified: No

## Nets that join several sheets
3.3V_OUT: 12 to 3.3V (7 pins), Telemetry (R14.2), Connector (J1.LP2)
5V: 12V to 5V (9 pins), Telemetry (R9.2), Connector (J1.P3)
+12Vp: 12V Bias (D5.2 R78.2), 28V to 12 V (12Vp_EXT.1), 28V to 12V drivers (R201.1 R214.1)
+12Vs: 12V Bias (R77.2), 28V to 12 V (12Vs_EXT.1 D111.1 D112.1 R107.2), 28V to 12V drivers (R227.1), Telemetry (13 pins)
Chassis: 12V Bias (C1.2 C2.2), Connector (J1.LP1 J2.1 J4.1)
Input_Supply: 12V Bias (C6.1 T2.2), Connector (J1.P2)
PGND: 12V Bias (52 pins), 28V to 12 V (17 pins), 28V to 12V drivers (38 pins)
PVIN: 28V to 12 V (18 pins), 12V to 5V (14 pins), 12 to 3.3V (13 pins), Telemetry (R8.2), Connector (J1.P6)
SGND: 12V Bias (5 pins), 28V to 12 V (55 pins), 28V to 12V drivers (36 pins), 12V to 5V (39 pins), 12 to 3.3V (36 pins), Telemetry (53 pins), Connector (J1.P4 J1.P5)
VIN: 12V Bias (16 pins), 28V to 12 V (8 pins)
3.3V CS+: 12 to 3.3V (L1.2 R3.1), Telemetry (R12.2)
3.3V_EN: 12 to 3.3V (3.3V_EN.3), Telemetry (U1.6)
5V CS+: 12V to 5V (L2.2 R32.1), Telemetry (R5.2)
5V_EN: 12V to 5V (5V_EN.3), Telemetry (U1.4)
12V CS+: 28V to 12 V (L101.2 R1.1 R2.1), Telemetry (R4.2)
12V_EN: 28V to 12 V (12V_EN.3), Telemetry (U1.5)
Input Return: 12V Bias (C6.2 T2.1), Connector (J1.P1)
OUTA: 28V to 12 V (D113.1 Q109.2), 28V to 12V drivers (R204.2)
OUTB: 28V to 12 V (D114.1 Q110.2), 28V to 12V drivers (R217.2)
RS485_N: Telemetry (R82.2), Connector (J1.D5)
RS485_P: Telemetry (R81.2), Connector (J1.C5)
SRA: 28V to 12 V (C114.2 D108.1 R114.1), 28V to 12V drivers (R238.1)
SRB: 28V to 12 V (C113.2 D105.1 R113.1), 28V to 12V drivers (R237.1)
VG_HOA: 28V to 12 V (Q101.1), 28V to 12V drivers (R208.1 R209.1 R212.1)
VG_HOB: 28V to 12 V (Q103.1), 28V to 12V drivers (R221.1 R222.1 R225.1)
VG_LOA: 28V to 12 V (Q102.1), 28V to 12V drivers (R210.1 R211.1 R213.1)
VG_LOB: 28V to 12 V (Q104.1), 28V to 12V drivers (R223.1 R224.1 R226.1)
VG_SRA: 28V to 12 V (Q106.1), 28V to 12V drivers (R231.1 R232.1 R235.1)
VG_SRB: 28V to 12 V (Q105.1), 28V to 12V drivers (R233.1 R234.1 R236.1)
VS_HOA: 28V to 12 V (Q101.5), 28V to 12V drivers (21 pins)
VS_HOB: 28V to 12 V (Q103.5), 28V to 12V drivers (21 pins)

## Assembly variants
001: not fitted C7 C8 C10 C13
